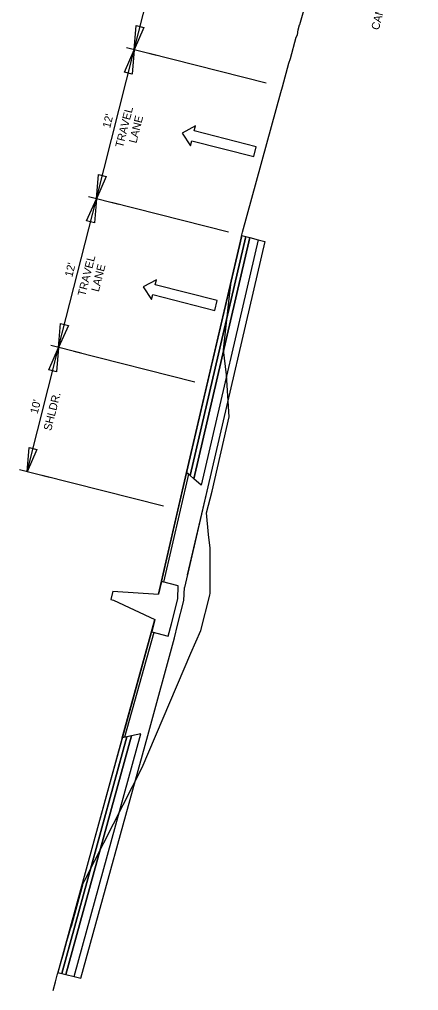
# Model space of a CAD drawing. Extents: x 670009 to 670131, y 737833 to 738002.
# Drawn here: x 670075.6 to 670106.8, y 737832.8 to 737908.7 of the extents above; entities that cross this region are included whole.
import ezdxf

# ---------------------------------------------------------------- set-up
doc = ezdxf.new("R2010")
doc.units = 0
for name, color, linetype in [('R_Alt Surface', 7, 'Continuous'), ('R_Exist Surface', 7, 'Continuous'), ('R_Fin Surface', 7, 'Continuous'), ('R_MOT', 7, 'Continuous'), ('R_SIGN_ANNOT', 7, 'Continuous')]:
    doc.layers.add(name, color=color, linetype=linetype)

msp = doc.modelspace()

# ---------------------------------------------------------------- linework, layer by layer
for points in [[(670086.151, 737861.794), (670085.906, 737860.825), (670087.198, 737860.497), (670087.444, 737861.466), (670087.936, 737863.405), (670087.967, 737864.428), (670086.674, 737864.756), (670086.429, 737863.787)], [(670082.871, 737863.998), (670082.871, 737863.998), (670082.709, 737863.358), (670082.924, 737863.304)], [(670082.871, 737863.998), (670086.429, 737863.787)], [(670082.924, 737863.304), (670086.151, 737861.794)]]:
    msp.add_lwpolyline(points)
at = {"layer": 'R_Alt Surface'}
for points in [[(670093.257, 737891.706), (670093.577, 737891.625), (670089.199, 737872.79), (670088.917, 737873.034)], [(670093.577, 737891.625), (670094.223, 737891.461), (670089.766, 737872.301), (670089.199, 737872.79)], [(670079.211, 737834.069), (670079.857, 737833.905), (670085.07, 737852.874), (670084.339, 737852.714)], [(670078.891, 737834.15), (670079.211, 737834.069), (670084.339, 737852.714), (670083.975, 737852.634)]]:
    msp.add_lwpolyline(points, close=True, dxfattribs=at)
for points in [[(670094.223, 737891.461), (670094.748, 737891.328), (670090.289, 737872.168), (670088.459, 737864.304)], [(670094.223, 737891.461), (670094.748, 737891.328), (670090.289, 737872.168), (670088.686, 737865.278)], [(670087.69, 737860.372), (670087.928, 737861.343), (670088.42, 737863.282), (670088.459, 737864.304)], [(670079.857, 737833.905), (670080.382, 737833.772), (670085.594, 737852.741), (670087.69, 737860.372)]]:
    msp.add_lwpolyline(points, dxfattribs=at)
at = {"layer": 'R_Exist Surface'}
msp.add_lwpolyline([(670078.218, 737832.812), (670078.381, 737833.489), (670078.511, 737834.015), (670078.522, 737834.048), (670078.54, 737834.106), (670078.643, 737834.444), (670078.846, 737835.088), (670078.982, 737835.614), (670079.27, 737836.678), (670079.432, 737837.197), (670079.572, 737837.667), (670079.618, 737837.782), (670079.652, 737837.853), (670080.53, 737841.078), (670080.557, 737841.179), (670080.684, 737841.443), (670085.15, 737850.242), (670088.974, 737859.175), (670089.748, 737860.951), (670090.438, 737863.703), (670090.472, 737863.842), (670090.48, 737863.889), (670090.466, 737867.363), (670090.343, 737868.448), (670090.182, 737870.135), (670090.627, 737871.83), (670091.964, 737877.64), (670091.759, 737880.904), (670091.51, 737882.856), (670092.036, 737887.536), (670092.082, 737887.948), (670092.082, 737887.958), (670092.09, 737887.99), (670092.461, 737889.663), (670092.483, 737889.753), (670092.803, 737891.055), (670092.809, 737891.083), (670092.926, 737891.731), (670092.947, 737891.839), (670092.95, 737891.853), (670093.007, 737892.064), (670095.997, 737902.966), (670096.118, 737903.406), (670096.626, 737905.253), (670096.744, 737905.619), (670097.204, 737907.281), (670097.286, 737907.457), (670097.29, 737907.465), (670097.351, 737907.845), (670097.356, 737907.87), (670097.462, 737908.238), (670097.466, 737908.246), (670097.476, 737908.287), (670098.668, 737912.529)], dxfattribs=at)
at = {"layer": 'R_Fin Surface'}
for points in [[(670092.937, 737891.788), (670090.22, 737880.097), (670087.955, 737870.355), (670086.429, 737863.787)], [(670088.776, 737873.155), (670086.836, 737864.715), (670086.674, 737864.756), (670086.429, 737863.787), (670088.635, 737873.277), (670088.776, 737873.155)], [(670086.151, 737861.794), (670084.406, 737855.448), (670081.754, 737845.804), (670078.571, 737834.231)], [(670083.61, 737852.555), (670086.151, 737861.794), (670085.906, 737860.825), (670086.067, 737860.784), (670083.792, 737852.594), (670083.61, 737852.555)]]:
    msp.add_lwpolyline(points, dxfattribs=at)
for points in [[(670092.937, 737891.788), (670093.257, 737891.706), (670088.917, 737873.034), (670088.635, 737873.277)], [(670078.571, 737834.231), (670078.891, 737834.15), (670083.975, 737852.634), (670083.61, 737852.555)]]:
    msp.add_lwpolyline(points, close=True, dxfattribs=at)
at = {"layer": 'R_MOT'}
for p, q in [((670089.328, 737900.347), (670088.281, 737899.787)), ((670089.229, 737899.959), (670089.328, 737900.347)), ((670094.072, 737898.731), (670089.229, 737899.959)), ((670088.281, 737899.787), (670088.934, 737898.796)), ((670088.934, 737898.796), (670089.033, 737899.184)), ((670089.033, 737899.184), (670093.875, 737897.955)), ((670093.875, 737897.955), (670094.072, 737898.731)), ((670086.282, 737888.339), (670085.235, 737887.779)), ((670085.235, 737887.779), (670085.889, 737886.788)), ((670086.184, 737887.951), (670086.282, 737888.339)), ((670091.026, 737886.723), (670086.184, 737887.951)), ((670085.889, 737886.788), (670085.987, 737887.176)), ((670085.987, 737887.176), (670090.83, 737885.947)), ((670090.83, 737885.947), (670091.026, 737886.723))]:
    msp.add_line(p, q, dxfattribs=at)
at = {"layer": 'R_SIGN_ANNOT'}
for p, q in [((670084.537, 737906.298), (670087.487, 737917.93)), ((670081.586, 737894.666), (670084.537, 737906.298)), ((670086.287, 737905.854), (670083.931, 737906.452)), ((670094.855, 737903.681), (670085.718, 737905.998)), ((670078.636, 737883.035), (670081.586, 737894.666)), ((670083.337, 737894.222), (670080.981, 737894.82)), ((670091.905, 737892.049), (670082.768, 737894.367)), ((670080.387, 737882.591), (670078.031, 737883.188)), ((670076.178, 737873.341), (670078.636, 737883.035)), ((670089.282, 737880.335), (670079.818, 737882.735)), ((670077.929, 737872.897), (670075.572, 737873.495)), ((670086.824, 737870.641), (670077.36, 737873.042))]:
    msp.add_line(p, q, dxfattribs=at)
for points in [[(670085.3, 737908.039), (670084.537, 737906.298), (670084.695, 737908.192)], [(670083.773, 737904.557), (670084.537, 737906.298), (670084.379, 737904.404)], [(670082.35, 737896.407), (670081.586, 737894.666), (670081.745, 737896.561)], [(670080.823, 737892.926), (670081.586, 737894.666), (670081.428, 737892.772)], [(670079.4, 737884.775), (670078.636, 737883.035), (670078.794, 737884.929)], [(670077.873, 737881.294), (670078.636, 737883.035), (670078.478, 737881.14)], [(670076.942, 737875.082), (670076.178, 737873.341), (670076.336, 737875.236)]]:
    msp.add_lwpolyline(points, close=True, dxfattribs=at)

# ---------------------------------------------------------------- texts
for s, p in [('CANTILEVER AT STA1279+50SB', (670103.649, 737907.799)), ('TRAVEL', (670083.655, 737898.611)), ("12'", (670082.652, 737900.139)), ('LANE', (670084.71, 737898.957)), ('TRAVEL', (670080.712, 737887.006)), ("12'", (670079.702, 737888.507)), ('LANE', (670081.767, 737887.353)), ('SHLDR.', (670078.047, 737876.499)), ("10'", (670076.992, 737877.821))]:
    msp.add_text(s, height=0.625, rotation=75.76855, dxfattribs=at).set_placement(p)

doc.saveas('drawing.dxf')
